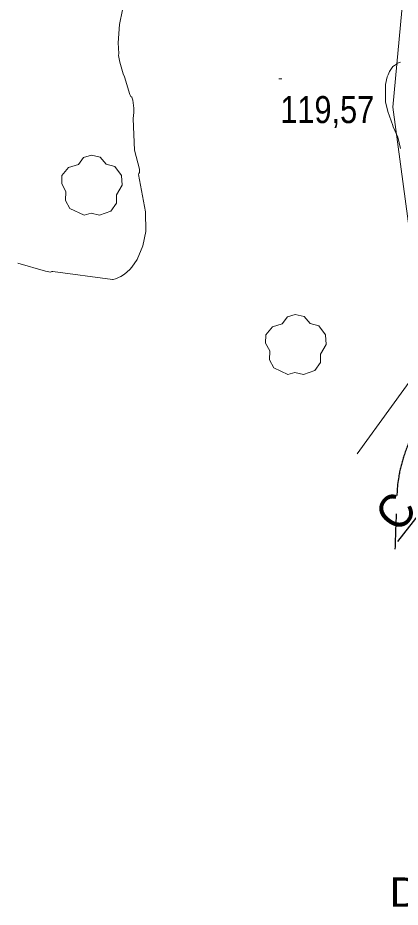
# Model space of a CAD drawing. Extents: x 480264 to 484872, y 4381275 to 4384491.
# Drawn here: x 483787.7 to 483911.4, y 4383312.2 to 4383600 of the extents above; entities that cross this region are included whole.
import ezdxf
from ezdxf.enums import TextEntityAlignment as Align

# ---------------------------------------------------------------- set-up
doc = ezdxf.new("R2010")
doc.units = 0
doc.header["$LTSCALE"] = 4
doc.linetypes.add('LONG_DASHED', pattern=[7.5, 6, -1.5])
for name, color, linetype, lineweight in [('29', 7, 'Continuous', 13), ('36', 7, 'Continuous', 25), ('38', 7, 'Continuous', 25), ('51', 7, 'Continuous', 13), ('7', 7, 'Continuous', 13), ('9', 7, 'Continuous', 13)]:
    doc.layers.add(name, color=color, linetype=linetype, lineweight=lineweight)
doc.layers.add('5', color=7, linetype='Continuous')

msp = doc.modelspace()

# ---------------------------------------------------------------- linework, layer by layer
at = {"layer": '29'}
for points in [[(483809.11, 4383536.21), (483804.57, 4383538.33), (483803.16, 4383540.87), (483803.26, 4383543.85), (483801.89, 4383546.26), (483801.93, 4383549.01), (483804.09, 4383551.61), (483807.28, 4383552.61), (483808.93, 4383554.8), (483811.5, 4383555.63), (483814.36, 4383554.98), (483816.31, 4383552.71), (483819.12, 4383551.89), (483821.25, 4383549.04), (483821.49, 4383545.91), (483819.61, 4383542.76), (483819.61, 4383540.08), (483817.79, 4383537.47), (483814.17, 4383536.13), (483811.4, 4383536.76)], [(483875.07, 4383484.63), (483870.53, 4383486.75), (483869.12, 4383489.29), (483869.22, 4383492.27), (483867.85, 4383494.68), (483867.89, 4383497.43), (483870.05, 4383500.03), (483873.24, 4383501.03), (483874.89, 4383503.22), (483877.46, 4383504.05), (483880.32, 4383503.4), (483882.27, 4383501.13), (483885.08, 4383500.31), (483887.21, 4383497.46), (483887.45, 4383494.33), (483885.57, 4383491.18), (483885.57, 4383488.5), (483883.75, 4383485.89), (483880.13, 4383484.55), (483877.36, 4383485.18)]]:
    msp.add_lwpolyline(points, close=True, dxfattribs=at)
at = {"layer": '36'}
msp.add_lwpolyline([(484099.22, 4383530.22), (484047.89, 4383521.9), (484037.73, 4383519.8), (484025.74, 4383517), (484011.29, 4383513.64), (484005.14, 4383511.78), (483993.08, 4383506.03), (483980.57, 4383498.74), (483966.62, 4383488.78), (483953.28, 4383478.28), (483940.37, 4383466.32), (483927.64, 4383452.44), (483910.51, 4383430.56)], dxfattribs=at)
at = {"layer": '38', "linetype": 'LONG_DASHED'}
msp.add_spline([(483948.27, 4383681.37), (483947.44, 4383677.16), (483943.11, 4383666.53), (483939.8, 4383660.47), (483937.44, 4383656.41), (483936.14, 4383650.27), (483939.31, 4383645.47), (483946.37, 4383638.42), (483950.03, 4383631.6), (483949.26, 4383627.51), (483946.12, 4383622.55), (483939.76, 4383618.01), (483933.67, 4383615.11), (483929.9, 4383611.7), (483929.15, 4383610.18), (483929.59, 4383603.96), (483932.34, 4383598.76), (483934.21, 4383596.54), (483940.72, 4383587.86), (483942.8, 4383584.16), (483943.86, 4383576.69), (483943.51, 4383570.58), (483939.45, 4383564.12), (483937.16, 4383558.18), (483936.44, 4383551.38), (483935.04, 4383541.91), (483934.28, 4383539.06), (483927.5, 4383518.84), (483926.82, 4383507.52), (483926.68, 4383503.83), (483926.32, 4383500.62), (483925.18, 4383491.33), (483922.04, 4383480.47), (483920.1, 4383475.28), (483915.05, 4383464.63), (483912.46, 4383457.87), (483910.9, 4383451.49), (483910.15, 4383441.41), (483909.68, 4383428.1)], degree=3, dxfattribs=at)
at = {"layer": '51'}
msp.add_lwpolyline([(483923.21, 4383715.44), (483915.26, 4383638.48), (483909.01, 4383571.13), (483917.15, 4383510.19), (483919.72, 4383489.5), (483897.5, 4383458.91)], dxfattribs=at)
at = {"layer": '7'}
msp.add_line((483872.09, 4383580.33), (483873.09, 4383580.33), dxfattribs=at)
at = {"layer": '9'}
for points in [[(483829.04, 4383537.29), (483826.78, 4383549.36), (483826.81, 4383549.54), (483826.84, 4383549.61), (483827.04, 4383549.99), (483827.08, 4383550.71), (483827.04, 4383551.04), (483825.48, 4383557.19), (483824.97, 4383567.35), (483825.1, 4383568.55), (483825.25, 4383569.24), (483825.27, 4383569.47), (483825.24, 4383570.75), (483824.88, 4383573.33), (483824.68, 4383574.06), (483824.54, 4383574.33), (483824.27, 4383574.6), (483823.9, 4383575.21), (483822.25, 4383580.93), (483821.81, 4383581.88), (483820.7, 4383585.66), (483820.27, 4383587.82), (483820.33, 4383588.5), (483820.18, 4383591.99), (483820.62, 4383597.89), (483821.58, 4383602.62)], [(483911.51, 4383585.64), (483910.89, 4383585.48), (483910.57, 4383585.33), (483910.38, 4383585.17), (483909.06, 4383584.29), (483907.97, 4383582.67), (483907.47, 4383581.63), (483907.22, 4383580.93), (483906.66, 4383578.46), (483906.62, 4383578.16), (483906.65, 4383572.83), (483907.34, 4383569.68), (483909, 4383565.18), (483909.02, 4383565.02), (483909.12, 4383564.72), (483910.59, 4383561.42), (483911.47, 4383557.79)], [(483787.69, 4383520.61), (483796.68, 4383518), (483798.23, 4383517.75), (483798.67, 4383517.88), (483799.02, 4383517.88), (483818.3, 4383515.31), (483818.43, 4383515.31), (483818.56, 4383515.33), (483819.31, 4383515.54), (483820.99, 4383516.3), (483822.16, 4383517.07), (483823.95, 4383518.54), (483824.61, 4383519.3), (483826.25, 4383521.81), (483828.17, 4383526.27), (483829.07, 4383530.92), (483829.04, 4383537.29)]]:
    msp.add_lwpolyline(points, dxfattribs=at)

# ---------------------------------------------------------------- texts
at = {"layer": '5', "width": 0.95}
msp.add_text('C', height=10.99, rotation=52.498, dxfattribs=at).set_placement((483914.256, 4383436.907), align=Align.CENTER)
at = {"layer": '5', "width": 1.15}
msp.add_text('Destacament de Pontir%', height=9.5, dxfattribs=at).set_placement((484069.41, 4383312.29), align=Align.RIGHT)
at = {"layer": '7', "width": 0.85}
msp.add_text('119,57', height=8.75, dxfattribs=at).set_placement((483872.59, 4383565.96))

doc.saveas('drawing.dxf')
